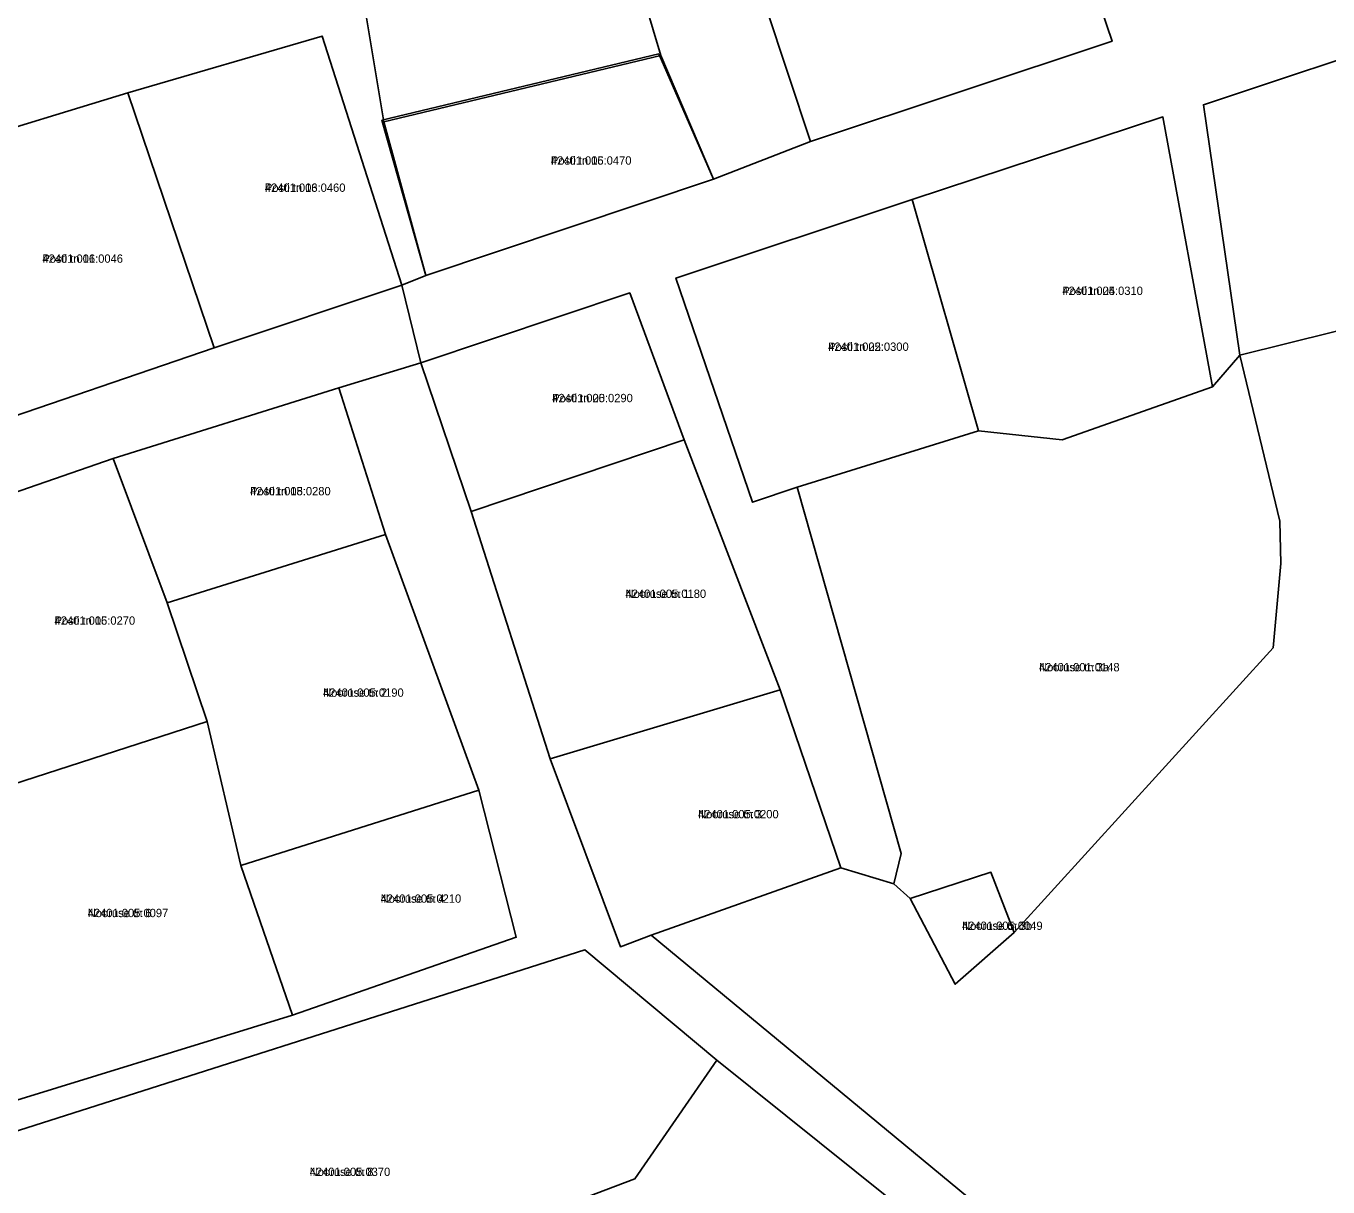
# Model space of a CAD drawing. Extents: x 595979 to 597983, y 6604231 to 6607350.
# Drawn here: x 597196.3 to 597430.6, y 6606349.2 to 6606558.1 of the extents above; entities that cross this region are included whole.
import ezdxf

# ---------------------------------------------------------------- set-up
doc = ezdxf.new("R2010")
doc.units = 0
for name, color, linetype in [('L_AADRESS', 7, 'Continuous'), ('PIIR', 7, 'Continuous'), ('TUNNUS', 7, 'Continuous')]:
    doc.layers.add(name, color=color, linetype=linetype)

msp = doc.modelspace()

# ---------------------------------------------------------------- linework, layer by layer
at = {"layer": 'PIIR'}
for points in [[(597297.3, 6606597.25), (597310.56, 6606552.82), (597260.71, 6606540.89), (597253.73, 6606583.05)], [(597325.44, 6606573.72), (597379.23, 6606592.26), (597391.78, 6606555.36), (597337.5, 6606537.33)], [(597414.73, 6606498.88), (597408.21, 6606543.96), (597447.13, 6606556.9), (597456.39, 6606524.74), (597434.89, 6606518), (597436.81, 6606516.67), (597438.63, 6606510.78), (597440.14, 6606505.19)], [(597214.68, 6606546.12), (597249.66, 6606556.3), (597263.96, 6606511.51), (597230.22, 6606500.23)], [(597310.23, 6606553.1), (597320.07, 6606530.57), (597268.29, 6606513.24), (597260.37, 6606541.17)], [(597168.37, 6606539.36), (597181.28, 6606543.65), (597183.62, 6606536.59), (597214.68, 6606546.12), (597230.22, 6606500.23), (597187.03, 6606485.44), (597169.62, 6606536.56)], [(597367.73, 6606485.27), (597355.77, 6606526.9), (597400.92, 6606541.76), (597409.84, 6606493.22), (597382.76, 6606483.64)], [(597327.04, 6606472.44), (597313.28, 6606512.77), (597355.77, 6606526.9), (597367.73, 6606485.27), (597335.09, 6606475.14)], [(597421.94, 6606469.06), (597414.73, 6606498.88), (597440.14, 6606505.19), (597460.45, 6606510.21), (597490.98, 6606521.6), (597497.25, 6606509.28), (597526.35, 6606475.79), (597503.72, 6606456.98), (597525.56, 6606431.86), (597544.98, 6606446.72), (597555.81, 6606443.42), (597479.92, 6606388.47), (597432.66, 6606344.54), (597405, 6606315.04), (597308.82, 6606394.53), (597342.93, 6606406.67), (597352.48, 6606403.76), (597355.41, 6606401.16), (597363.55, 6606385.72), (597374.14, 6606395), (597420.74, 6606446.26), (597422.14, 6606461.42)], [(597267.39, 6606497.51), (597304.98, 6606510.09), (597314.78, 6606483.66), (597276.42, 6606470.77)], [(597367.73, 6606485.27), (597382.76, 6606483.64), (597409.84, 6606493.22), (597414.73, 6606498.88), (597421.94, 6606469.06), (597422.14, 6606461.42), (597420.74, 6606446.26), (597374.14, 6606395), (597369.96, 6606405.87), (597355.41, 6606401.16), (597352.48, 6606403.76), (597353.83, 6606409.23), (597335.09, 6606475.14)], [(597212.02, 6606480.33), (597252.65, 6606493), (597261.05, 6606466.64), (597221.77, 6606454.36)], [(597276.42, 6606470.77), (597314.78, 6606483.66), (597332.02, 6606438.68), (597290.63, 6606426.26)], [(597174.04, 6606467.2), (597212.02, 6606480.33), (597221.77, 6606454.36), (597228.92, 6606432.96), (597187.57, 6606419.63)], [(597221.77, 6606454.36), (597261.05, 6606466.64), (597277.83, 6606420.62), (597235.02, 6606407.08), (597228.92, 6606432.96)], [(597290.63, 6606426.26), (597332.02, 6606438.68), (597342.93, 6606406.67), (597308.82, 6606394.53), (597303.29, 6606392.45)], [(597171.57, 6606414.32), (597187.57, 6606419.63), (597228.92, 6606432.96), (597235.02, 6606407.08), (597244.31, 6606380.13), (597187.46, 6606362.63)], [(597235.02, 6606407.08), (597277.83, 6606420.62), (597284.55, 6606394.16), (597244.31, 6606380.13)], [(597369.96, 6606405.87), (597374.14, 6606395), (597363.55, 6606385.72), (597355.41, 6606401.16)], [(597186.67, 6606356.79), (597296.9, 6606391.91), (597320.66, 6606372.05), (597305.91, 6606350.72), (597286.26, 6606343.26), (597250.13, 6606310.53), (597238.31, 6606326.16), (597201.01, 6606313.35)], [(597261.65, 6606288.8), (597250.13, 6606310.53), (597286.26, 6606343.26), (597305.91, 6606350.72), (597320.66, 6606372.05), (597351.53, 6606347.3), (597286.06, 6606268.5), (597280.89, 6606272.79)]]:
    msp.add_lwpolyline(points, close=True, dxfattribs=at)
for points in [[(597325.44, 6606573.72), (597337.5, 6606537.33), (597320.07, 6606530.57), (597310.56, 6606552.82), (597297.3, 6606597.25)], [(597447.13, 6606556.9), (597408.21, 6606543.96), (597414.73, 6606498.88), (597409.84, 6606493.22), (597400.92, 6606541.76), (597355.77, 6606526.9), (597313.28, 6606512.77), (597327.04, 6606472.44), (597335.09, 6606475.14), (597353.83, 6606409.23), (597352.48, 6606403.76), (597342.93, 6606406.67), (597332.06, 6606438.7), (597314.78, 6606483.66), (597304.98, 6606510.09), (597267.39, 6606497.51), (597263.96, 6606511.51), (597268.29, 6606513.24), (597320.07, 6606530.57), (597337.5, 6606537.33), (597391.78, 6606555.36), (597379.23, 6606592.26)], [(597253.73, 6606583.05), (597260.71, 6606540.89), (597268.29, 6606513.24), (597263.96, 6606511.51), (597249.66, 6606556.3), (597214.68, 6606546.12), (597183.62, 6606536.59), (597181.28, 6606543.65), (597168.37, 6606539.36), (597169.62, 6606536.56), (597144.22, 6606528.17), (597144.75, 6606551.47), (597187.35, 6606568.17)], [(597187.03, 6606485.44), (597230.22, 6606500.23), (597263.96, 6606511.51), (597267.39, 6606497.51), (597252.65, 6606493), (597212.02, 6606480.33), (597174.04, 6606467.2)], [(597441.43, 6606253.64), (597413.23, 6606283.67), (597400.46, 6606298.74), (597369.25, 6606325.59), (597373.25, 6606330.04), (597351.53, 6606347.3), (597320.66, 6606372.05), (597296.9, 6606391.91), (597186.67, 6606356.79), (597187.46, 6606362.63), (597244.31, 6606380.13), (597284.55, 6606394.16), (597277.83, 6606420.62), (597261.05, 6606466.64), (597252.65, 6606493), (597267.39, 6606497.51), (597276.42, 6606470.77), (597290.63, 6606426.26), (597303.29, 6606392.45), (597308.82, 6606394.53), (597405, 6606315.04), (597418.56, 6606303.86), (597449.96, 6606275.13)]]:
    msp.add_lwpolyline(points, dxfattribs=at)

# ---------------------------------------------------------------- texts
at = {"layer": 'L_AADRESS'}
for s, p in [('Posti tn 15', (597290.79, 6606533.17)), ('Posti tn 13', (597239.32, 6606528.28)), ('Posti tn 11', (597199.29, 6606515.52)), ('Posti tn 24', (597382.81, 6606509.73)), ('Posti tn 22', (597340.67, 6606499.67)), ('Posti tn 20', (597291.03, 6606490.43)), ('Posti tn 18', (597236.66, 6606473.68)), ('Nooruse tn 1', (597304.22, 6606455.22)), ('Posti tn 16', (597201.48, 6606450.4)), ('Nooruse tn 3a', (597378.62, 6606442.01)), ('Nooruse tn 2', (597249.8, 6606437.44)), ('Nooruse tn 3', (597317.27, 6606415.57)), ('Nooruse tn 4', (597260.15, 6606400.38)), ('Nooruse tn 6', (597207.44, 6606397.79)), ('Nooruse tn 3b', (597364.77, 6606395.49)), ('Nooruse tn 8', (597247.38, 6606351.22))]:
    msp.add_text(s, height=1.5, dxfattribs=at).set_placement(p)
at = {"layer": 'TUNNUS'}
for s, p in [('42401:006:0470', (597290.79, 6606533.17)), ('42401:006:0460', (597239.32, 6606528.28)), ('42401:006:0046', (597199.29, 6606515.52)), ('42401:005:0310', (597382.81, 6606509.73)), ('42401:005:0300', (597340.67, 6606499.67)), ('42401:005:0290', (597291.03, 6606490.43)), ('42401:005:0280', (597236.66, 6606473.68)), ('42401:005:0180', (597304.22, 6606455.22)), ('42401:005:0270', (597201.48, 6606450.4)), ('42401:001:0148', (597378.62, 6606442.01)), ('42401:005:0190', (597249.8, 6606437.44)), ('42401:005:0200', (597317.27, 6606415.57)), ('42401:005:0210', (597260.15, 6606400.38)), ('42401:005:0097', (597207.44, 6606397.79)), ('42401:005:0049', (597364.77, 6606395.49)), ('42401:005:0370', (597247.38, 6606351.22))]:
    msp.add_text(s, height=1.5, dxfattribs=at).set_placement(p)

doc.saveas('drawing.dxf')
